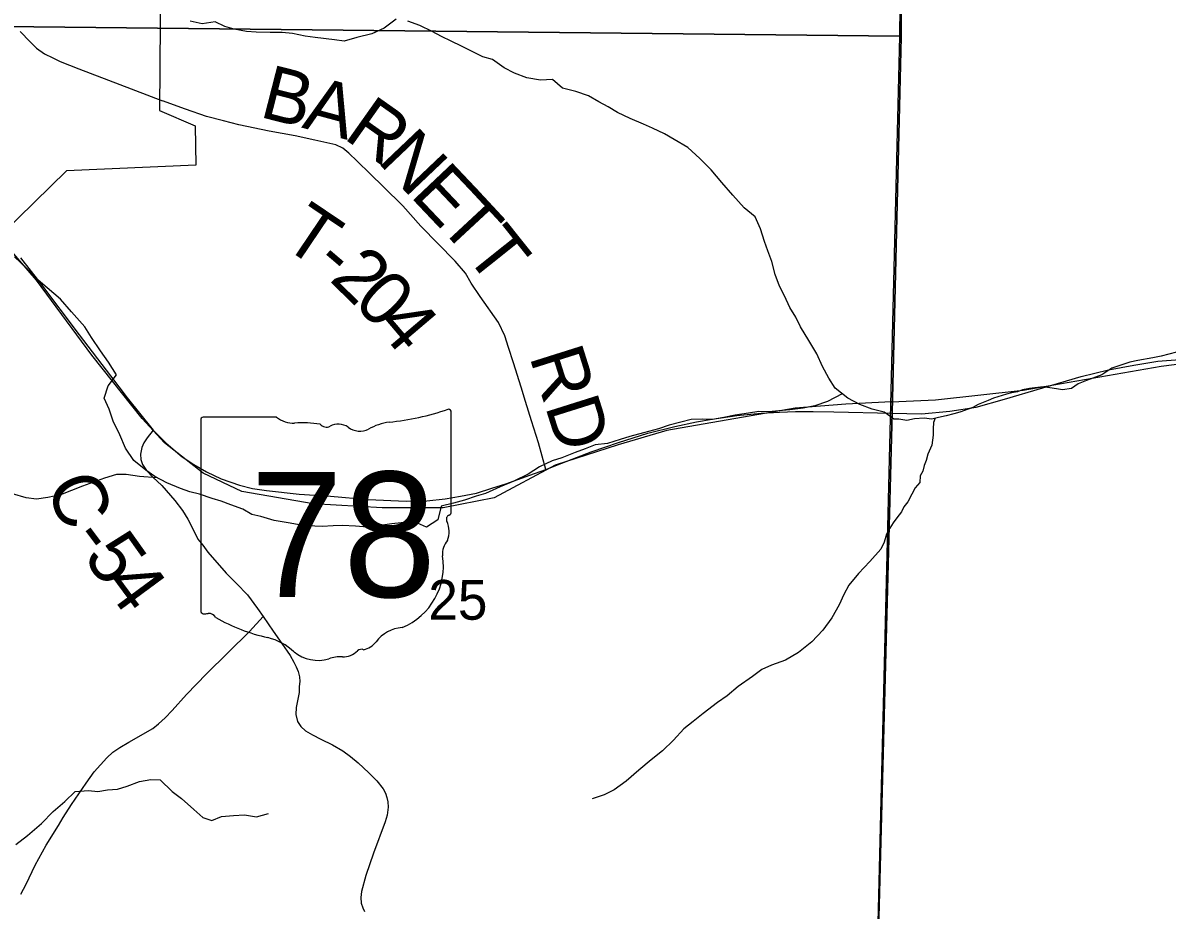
# Model space of a CAD drawing. Extents: x 0 to 191, y 0 to 55.
# Drawn here: x 147 to 147.603, y 18.986 to 19.453 of the extents above; entities that cross this region are included whole.
import ezdxf

# ---------------------------------------------------------------- set-up
doc = ezdxf.new("R2010")
doc.units = 0
for name, color, linetype in [('GM_X_City_Street', 7, 'Continuous'), ('GM_X_Corporation', 7, 'Continuous'), ('GM_X_County_Road', 7, 'Continuous'), ('GM_X_County_Road_Text', 7, 'Continuous'), ('GM_X_Minor_River', 7, 'Continuous'), ('GM_X_Rail_Line', 7, 'Continuous'), ('GM_X_Section_Text', 7, 'Continuous'), ('GM_X_State_Location', 7, 'Continuous'), ('GM_X_State_Route', 7, 'Continuous'), ('GM_X_State_Shield', 7, 'Continuous'), ('GM_X_Township_Road', 7, 'Continuous'), ('GM_X_Township_Road_Text', 7, 'Continuous')]:
    doc.layers.add(name, color=color, linetype=linetype)

msp = doc.modelspace()

# ---------------------------------------------------------------- linework, layer by layer
at = {"layer": 'GM_X_City_Street'}
msp.add_lwpolyline([(146.9989, 19.44827), (147.0041, 19.44279), (147.00736, 19.43954), (147.01172, 19.43656), (147.01595, 19.43441), (147.01996, 19.43254), (147.0298, 19.42859), (147.05128, 19.42048), (147.07373, 19.41175)], dxfattribs=at)
at = {"layer": 'GM_X_Corporation'}
for points in [[(146.94931, 22.06201), (147.41583, 22.05521), (147.41793, 22.05518), (147.49329, 22.05409), (147.49076, 21.86656), (147.48909, 21.69468), (147.48205, 21.22082), (147.48076, 21.17388), (147.48135, 21.17107), (147.48116, 21.16643), (147.48019, 21.14187), (147.48058, 21.10512), (147.48017, 21.08849), (147.4775, 21.04138), (147.47544, 20.87227), (147.47203, 20.22876), (147.46245, 19.50336), (147.46245, 19.44524), (147.45775, 19.24764), (147.44948, 18.93531), (147.29316, 18.93706), (147.2922, 18.93707), (146.93654, 18.94104)], [(147.48909, 21.69468), (147.48205, 21.22082), (147.48076, 21.17388), (147.48135, 21.17107), (147.48116, 21.16643), (147.48019, 21.14187), (147.48058, 21.10512), (147.48017, 21.08849), (147.4775, 21.04138), (147.47544, 20.87227), (147.47203, 20.22876), (147.46245, 19.50336), (147.46245, 19.44524), (147.45775, 19.24764), (147.44948, 18.93531), (147.44822, 18.85009), (147.44627, 18.74989), (147.4432, 18.61761), (150.07549, 18.61761), (150.07549, 22.0195)], [(143.27549, 18.61761), (147.4432, 18.61761), (147.44627, 18.74989), (147.44822, 18.85009), (147.44948, 18.93531), (147.45775, 19.24764), (147.46245, 19.44524), (147.46245, 19.50336), (147.47203, 20.22876), (147.47544, 20.87227), (147.4775, 21.04138), (147.48017, 21.08849), (147.48058, 21.10512), (147.48019, 21.14187), (147.48116, 21.16643), (147.48135, 21.17107), (147.48076, 21.17388), (147.48205, 21.22082), (147.48909, 21.69468)], [(148.46737, 18.92047), (148.27305, 18.92256), (148.01108, 18.92749), (147.65574, 18.93245), (147.44948, 18.93531), (147.45775, 19.24764), (147.46245, 19.44524), (147.46245, 19.50336), (147.47203, 20.22876), (147.47544, 20.87227), (147.4775, 21.04138), (147.48017, 21.08849), (147.48058, 21.10512), (147.48019, 21.14187), (147.48116, 21.16643), (147.48135, 21.17107), (147.48076, 21.17388), (147.48205, 21.22082), (147.48909, 21.69468)], [(146.80243, 19.70554), (147.07447, 19.70651), (147.0743, 19.68431), (147.07222, 19.40664), (147.09099, 19.39871), (147.09138, 19.378), (147.02315, 19.37496), (146.98931, 19.3417)]]:
    msp.add_lwpolyline(points, dxfattribs=at)
for points in [[(146.95813, 19.96302), (147.4674, 19.95893), (147.46171, 19.44593), (146.95709, 19.45123)], [(146.95709, 19.45123), (147.46171, 19.44593), (147.44914, 18.93607), (146.94939, 18.94162)]]:
    msp.add_lwpolyline(points, close=True, dxfattribs=at)
at = {"layer": 'GM_X_County_Road'}
for points in [[(147.06882, 19.23844), (147.06568, 19.23442), (147.06387, 19.2318), (147.06286, 19.22934), (147.06222, 19.22576), (147.0623, 19.2229), (147.06322, 19.22032), (147.06532, 19.2171), (147.06866, 19.21367), (147.07333, 19.20928), (147.0803, 19.20143), (147.08433, 19.19615), (147.08715, 19.19156), (147.09009, 19.18584), (147.09242, 19.18101), (147.09496, 19.17787), (147.09762, 19.17424), (147.10733, 19.16321), (147.11276, 19.15761), (147.11852, 19.15169), (147.1238, 19.1446), (147.12679, 19.14026), (147.13202, 19.13264), (147.13657, 19.12611), (147.14094, 19.11972), (147.14289, 19.11628), (147.14415, 19.11375), (147.1451, 19.11145), (147.14591, 19.10851), (147.14609, 19.10607), (147.14573, 19.10354), (147.1456, 19.10024), (147.14474, 19.0959), (147.14402, 19.09233), (147.14388, 19.08871), (147.14487, 19.08505), (147.14659, 19.08243), (147.14908, 19.08017), (147.15278, 19.07804), (147.15717, 19.07578), (147.16323, 19.07271), (147.16865, 19.06959), (147.17276, 19.06661), (147.17665, 19.06331), (147.18239, 19.05797), (147.1866, 19.05373), (147.18994, 19.04961), (147.19116, 19.04731), (147.19179, 19.04496), (147.19234, 19.04279), (147.19261, 19.03994), (147.19202, 19.03569), (147.19102, 19.03216), (147.18474, 19.0158), (147.18072, 19.00396), (147.17841, 18.9955), (147.17814, 18.9923), (147.17837, 18.9894), (147.17918, 18.98696), (147.18013, 18.98493)], [(146.9991, 18.99409), (147.00204, 18.99944), (147.0068, 19.00939), (147.0126, 19.0199), (147.019, 19.0303), (147.0215, 19.03452), (147.02589, 19.04133), (147.03358, 19.05249), (147.03785, 19.05853), (147.04437, 19.06598), (147.04768, 19.06888), (147.0513, 19.07134), (147.05601, 19.07408), (147.06874, 19.08129), (147.07172, 19.08378), (147.07523, 19.08704), (147.07877, 19.09083), (147.0863, 19.09921), (147.09693, 19.1102), (147.11961, 19.13248), (147.12679, 19.14026)]]:
    msp.add_lwpolyline(points, dxfattribs=at)
at = {"layer": 'GM_X_Minor_River'}
for points in [[(147.19682, 19.45481), (147.19042, 19.45003), (147.184, 19.44714), (147.17606, 19.4452), (147.16945, 19.44326), (147.16433, 19.44399), (147.15411, 19.44506), (147.14881, 19.44579), (147.14217, 19.44727), (147.13668, 19.4478), (147.13044, 19.44777), (147.12305, 19.44791), (147.11794, 19.44826), (147.1115, 19.44955), (147.10657, 19.45085), (147.10145, 19.45347), (147.09464, 19.45229), (147.08839, 19.45377)], [(147.45362, 19.24798), (147.44727, 19.24953), (147.44082, 19.25196), (147.43437, 19.25533), (147.42771, 19.26061), (147.42446, 19.26571), (147.42121, 19.27195), (147.41814, 19.27857), (147.41394, 19.28557), (147.40955, 19.29275), (147.40705, 19.29786), (147.404, 19.30296), (147.40112, 19.3092), (147.39844, 19.31431), (147.39614, 19.32037), (147.39439, 19.32719), (147.39228, 19.33286), (147.39055, 19.33779), (147.38842, 19.34441), (147.38574, 19.35066), (147.37984, 19.35555), (147.37394, 19.36216), (147.36822, 19.36876), (147.3625, 19.37556), (147.3566, 19.38141), (147.35032, 19.38725), (147.34311, 19.39138), (147.33798, 19.39438), (147.33172, 19.39738), (147.32697, 19.39944), (147.31995, 19.40243), (147.31331, 19.40562), (147.30837, 19.40862), (147.30344, 19.41125), (147.29793, 19.41444), (147.29129, 19.41668), (147.28428, 19.41853), (147.27895, 19.42305), (147.27271, 19.42264), (147.26551, 19.42392), (147.25906, 19.42635), (147.25356, 19.42916), (147.24748, 19.43349), (147.24236, 19.43497), (147.23647, 19.43797), (147.23116, 19.4406), (147.22566, 19.44322), (147.22053, 19.44566), (147.2156, 19.44828), (147.20914, 19.45147), (147.20289, 19.45371)], [(147.43152, 19.25759), (147.42378, 19.25356), (147.41717, 19.25125), (147.41093, 19.25007), (147.40393, 19.24908), (147.39807, 19.24866), (147.39296, 19.24806), (147.38766, 19.24822), (147.38218, 19.24743), (147.37518, 19.24625), (147.36914, 19.24507), (147.36327, 19.24409), (147.35778, 19.24425), (147.35192, 19.24402), (147.34663, 19.24266), (147.34039, 19.24111), (147.33473, 19.23917), (147.32698, 19.23704), (147.3198, 19.2351), (147.3147, 19.23355), (147.3079, 19.23142), (147.30147, 19.23062), (147.29618, 19.22851), (147.29089, 19.22658), (147.28391, 19.22388), (147.2788, 19.22233), (147.2722, 19.21906), (147.26617, 19.21523), (147.25862, 19.21158), (147.25144, 19.2085), (147.24371, 19.20504), (147.23879, 19.20368), (147.23275, 19.20156), (147.22689, 19.20001), (147.22046, 19.19845), (147.21862, 19.19123), (147.21277, 19.1874), (147.20632, 19.19021), (147.19932, 19.1896), (147.1944, 19.18919), (147.18684, 19.188), (147.18173, 19.1874), (147.1753, 19.18793), (147.16848, 19.18827), (147.16356, 19.18805), (147.1577, 19.18764), (147.15013, 19.18797), (147.14482, 19.1887), (147.1399, 19.18962), (147.13251, 19.1909), (147.12549, 19.19294), (147.12076, 19.19405), (147.11601, 19.19687), (147.10975, 19.19911), (147.10463, 19.20097), (147.09989, 19.20246), (147.09325, 19.2047), (147.08814, 19.206), (147.08321, 19.20767), (147.076, 19.21067), (147.06973, 19.21404), (147.06498, 19.21743), (147.05871, 19.22251), (147.05431, 19.22894), (147.05125, 19.23594), (147.0478, 19.24312), (147.04568, 19.24956), (147.04299, 19.25524), (147.04523, 19.2617), (147.04955, 19.26761), (147.04534, 19.27422), (147.04115, 19.28027), (147.03637, 19.28726), (147.03294, 19.29274), (147.02589, 19.30066), (147.01998, 19.30746), (147.01313, 19.3133), (147.00838, 19.31744), (147.0021, 19.32367), (146.99582, 19.3297)], [(147.60752, 19.27955), (147.59941, 19.27734), (147.59507, 19.27652), (147.58715, 19.27508), (147.58281, 19.27426), (147.57339, 19.27108), (147.56814, 19.26759), (147.56005, 19.26462), (147.55572, 19.26285), (147.55216, 19.26033), (147.54744, 19.25969), (147.54422, 19.26022), (147.5372, 19.26126), (147.53002, 19.2604), (147.52644, 19.25959), (147.5238, 19.2586), (147.5206, 19.25799), (147.51795, 19.25738), (147.51117, 19.25519), (147.50835, 19.25401), (147.50309, 19.25185), (147.50027, 19.25029), (147.49349, 19.24791), (147.49029, 19.2471), (147.48614, 19.24591), (147.48218, 19.24509), (147.4786, 19.24428), (147.47461, 19.24479), (147.46951, 19.24434), (147.46555, 19.24353), (147.46138, 19.24422), (147.45873, 19.24419), (147.45654, 19.24583), (147.45362, 19.24798)], [(147.4805, 19.24471), (147.47957, 19.24239), (147.47943, 19.23916), (147.47929, 19.23574), (147.47895, 19.23307), (147.47861, 19.2306), (147.4766, 19.22582), (147.4757, 19.22238), (147.4746, 19.2199), (147.47389, 19.21685), (147.4726, 19.21436), (147.47227, 19.21093), (147.46985, 19.20805), (147.4682, 19.2048), (147.46599, 19.20077), (147.46394, 19.19808), (147.46266, 19.19541), (147.46024, 19.19233), (147.45839, 19.18964), (147.45654, 19.18677), (147.45488, 19.1837), (147.45352, 19.17944), (147.45177, 19.17572)], [(147.07102, 19.21335), (147.06159, 19.21399), (147.05458, 19.21509), (147.04948, 19.21506), (147.04324, 19.21312), (147.03739, 19.211), (147.03172, 19.20888), (147.02587, 19.20657), (147.02001, 19.20445), (147.0134, 19.20289), (147.00735, 19.20209), (147.00205, 19.20282), (146.99484, 19.20486)], [(147.45177, 19.17572), (147.44604, 19.16928), (147.44002, 19.16298), (147.43494, 19.15688), (147.43232, 19.15193), (147.42989, 19.14642), (147.42596, 19.13956), (147.42127, 19.13308), (147.41544, 19.12698), (147.40847, 19.12144), (147.40168, 19.11741), (147.39431, 19.11471), (147.38921, 19.1124), (147.38432, 19.10877), (147.37678, 19.10341), (147.37094, 19.09863), (147.36585, 19.095), (147.35831, 19.08926), (147.35304, 19.08506), (147.34814, 19.08123), (147.34269, 19.07513), (147.33685, 19.06959), (147.33101, 19.06481), (147.32442, 19.05946), (147.31783, 19.05354), (147.31142, 19.04914), (147.30614, 19.04645), (147.29991, 19.04433)], [(146.99649, 19.0203), (147.00271, 19.02508), (147.01005, 19.03138), (147.01626, 19.03768), (147.02228, 19.04284), (147.02774, 19.04818), (147.03474, 19.04879), (147.03966, 19.04825), (147.04477, 19.04904), (147.05006, 19.04945), (147.05517, 19.051), (147.06158, 19.05351), (147.06764, 19.05449), (147.07256, 19.05433), (147.07884, 19.04811), (147.08378, 19.04454), (147.09025, 19.03869), (147.095, 19.03455), (147.09974, 19.03287), (147.10484, 19.03499), (147.11108, 19.0356), (147.11695, 19.03582), (147.1232, 19.03491), (147.12962, 19.03666)]]:
    msp.add_lwpolyline(points, dxfattribs=at)
at = {"layer": 'GM_X_Rail_Line'}
for points in [[(147.45742, 19.25326), (147.48056, 19.25432), (147.52674, 19.2595), (147.59937, 19.27213), (147.65793, 19.27967), (147.70725, 19.28367), (147.73617, 19.29225), (147.77411, 19.32479), (147.80157, 19.38194), (147.80064, 19.39618), (147.79336, 19.42596), (147.78245, 19.45044), (147.74561, 19.51505)], [(147.45742, 19.25326), (147.43345, 19.25217), (147.40669, 19.25002), (147.33925, 19.23823), (147.31355, 19.23073), (147.28037, 19.22002), (147.24825, 19.20288), (147.22149, 19.19752), (147.18937, 19.19751), (147.15297, 19.19965), (147.1155, 19.20608), (147.09516, 19.21572), (147.07482, 19.23178), (147.06305, 19.24463), (147.03649, 19.27793), (147.00738, 19.31747), (146.96909, 19.36182)]]:
    msp.add_lwpolyline(points, dxfattribs=at)
at = {"layer": 'GM_X_State_Route'}
for points in [[(146.99906, 19.32911), (147.00897, 19.31638), (147.02991, 19.28859), (147.04643, 19.26696), (147.05513, 19.25536), (147.06882, 19.23844), (147.07555, 19.23176), (147.07937, 19.22837), (147.08413, 19.22443), (147.09025, 19.2204), (147.09686, 19.21656), (147.10471, 19.21281), (147.11426, 19.20949), (147.12109, 19.20779), (147.12845, 19.20657), (147.1457, 19.20476), (147.16218, 19.20359), (147.18206, 19.20194), (147.20195, 19.20096), (147.21282, 19.2013), (147.22252, 19.20223), (147.23061, 19.20364), (147.23909, 19.20525), (147.24708, 19.20783), (147.25444, 19.21017), (147.26702, 19.2148), (147.27555, 19.21776), (147.28395, 19.22107), (147.29939, 19.22696), (147.31378, 19.23196), (147.32912, 19.23679), (147.34345, 19.2404), (147.35484, 19.24273), (147.36306, 19.24423), (147.37606, 19.24612), (147.38884, 19.2474), (147.39845, 19.24796), (147.4069, 19.24829), (147.41628, 19.24823), (147.42717, 19.24801), (147.45785, 19.24737)], [(147.45785, 19.24737), (147.47321, 19.24693), (147.48812, 19.24836), (147.50194, 19.25055), (147.51696, 19.25472), (147.55732, 19.26667), (147.57157, 19.27018), (147.58506, 19.2727), (147.59757, 19.27467), (147.6207, 19.27643)]]:
    msp.add_lwpolyline(points, dxfattribs=at)
at = {"layer": 'GM_X_State_Shield'}
for p, q in [((147.22573, 19.19542), (147.22573, 19.24776)), ((147.0939, 19.24356), (147.0939, 19.1435)), ((147.13381, 19.24528), (147.0952, 19.24528)), ((147.22572, 19.19543), (147.22573, 19.19542))]:
    msp.add_line(p, q, dxfattribs=at)
for centre, radius, start, end in [((147.17877, 19.3817), 0.13981, 275.84447, 288.90645), ((147.22427, 19.24798), 0.00147, 351.86209, 97.738), ((147.09541, 19.24377), 0.00153, 98.1301, 188.1301), ((147.143, 19.2569), 0.01481, 231.61951, 271.11188), ((147.14791, 19.18911), 0.05318, 80.48669, 94.98827), ((147.15999, 19.24429), 0.00427, 219.79206, 297.10237), ((147.16626, 19.23273), 0.00889, 54.46668, 119.14113), ((147.19661, 19.21472), 0.02813, 97.34618, 120.76885), ((147.17773, 19.24859), 0.01069, 233.85621, 294.82819), ((147.2254, 19.19158), 0.00227, 107.94398, 210.33697), ((147.22417, 19.19522), 0.00157, 289.60381, 7.73413), ((147.21095, 19.18496), 0.01363, 340.03296, 23.64957), ((147.23099, 19.17351), 0.00992, 136.8065, 186.92959), ((147.1866, 19.16686), 0.03497, 292.30889, 8.98584), ((147.09542, 19.14328), 0.00154, 171.95839, 258.30661), ((147.09566, 19.15352), 0.01176, 267.33899, 280.60386), ((147.09806, 19.13773), 0.00424, 29.74838, 93.27175), ((147.15159, 19.22763), 0.10096, 240.41292, 257.1985), ((147.20135, 19.11541), 0.01915, 94.40312, 142.57675), ((147.12149, 19.09855), 0.03159, 47.18416, 75.83597), ((147.15566, 19.13723), 0.02004, 230.70037, 286.29184), ((147.16871, 19.12974), 0.01068, 268.77702, 315.54927), ((147.17837, 19.12005), 0.00301, 65.75173, 132.64842), ((147.17708, 19.1338), 0.0113, 282.87319, 323.27711), ((147.16724, 19.10264), 0.01647, 85.69512, 111.20995)]:
    msp.add_arc(centre, radius, start, end, dxfattribs=at)
at = {"layer": 'GM_X_Township_Road'}
msp.add_lwpolyline([(147.27555, 19.21776), (147.27167, 19.23182), (147.268, 19.24332), (147.26488, 19.25358), (147.26253, 19.26106), (147.25851, 19.27395), (147.25581, 19.28192), (147.25387, 19.28801), (147.25061, 19.29515), (147.24098, 19.3088), (147.23627, 19.31586), (147.23329, 19.32113), (147.22782, 19.32737), (147.2098, 19.34586), (147.20024, 19.35653), (147.19013, 19.36658), (147.18313, 19.37337), (147.17627, 19.38002), (147.17183, 19.38425), (147.16858, 19.38688), (147.16498, 19.38861), (147.15867, 19.39), (147.15396, 19.39111), (147.14364, 19.39332), (147.12992, 19.39589), (147.11398, 19.39921), (147.10581, 19.40122), (147.09687, 19.40358), (147.08585, 19.40739), (147.07373, 19.41175)], dxfattribs=at)

# ---------------------------------------------------------------- texts
at = {"layer": 'GM_X_County_Road_Text'}
for s, rotation, p in [('C', 292.67481, (147.01194, 19.20917)), ('-', 306.9809, (147.02477, 19.18093)), ('5', 305.41367, (147.03167, 19.17178)), ('4', 306.45333, (147.04214, 19.15706))]:
    msp.add_text(s, height=0.02841, rotation=rotation, dxfattribs=at).set_placement(p)
at = {"layer": 'GM_X_Section_Text'}
msp.add_text('25', height=0.020928, rotation=0.00001, dxfattribs=at).set_placement((147.21365, 19.13863))
at = {"layer": 'GM_X_State_Location'}
for s in ['s', 'r']:
    msp.add_text(s, height=0.0000947, dxfattribs=at).set_placement((147.15833, 19.18688))
msp.add_text('78', height=0.0000947, rotation=0.00001, dxfattribs=at).set_placement((147.13449, 19.17999))
at = {"layer": 'GM_X_State_Shield'}
msp.add_text('78', height=0.065918, dxfattribs=at).set_placement((147.11976, 19.15056))
at = {"layer": 'GM_X_Township_Road_Text'}
for s, height, rotation, p in [('B', 0.02841, 345.66368, (147.12413, 19.40354)), ('A', 0.02841, 344.9353, (147.14664, 19.39778)), ('R', 0.02841, 324.78672, (147.1684, 19.3924)), ('N', 0.02841, 313.58059, (147.18636, 19.37991)), ('E', 0.02841, 313.43007, (147.20358, 19.36181)), ('T', 0.02841, 312.88743, (147.21814, 19.34643)), ('T', 0.02841, 326.02586, (147.13564, 19.33609)), ('T', 0.02841, 308.58954, (147.23223, 19.33129)), ('-', 0.02841, 319.5528, (147.15258, 19.32473)), ('2', 0.02841, 315.4158, (147.16106, 19.31752)), ('0', 0.02841, 314.92273, (147.17348, 19.30528)), ('4', 0.02841, 310.31795, (147.18543, 19.29334)), ('RD', 0.028409, 287.50079, (147.26671, 19.27734))]:
    msp.add_text(s, height=height, rotation=rotation, dxfattribs=at).set_placement(p)

doc.saveas('drawing.dxf')
